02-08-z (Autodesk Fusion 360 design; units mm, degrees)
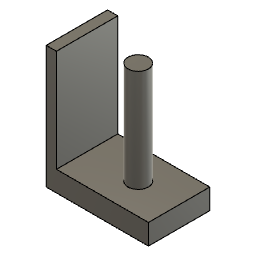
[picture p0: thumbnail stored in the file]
sketch "スケッチ1" plane through (0, 0, 0) normal (0, 1, 0) x axis (1, 0, 0)
  line L1 (50, 15) -> (0, 15)
  line L2 (50, -15) -> (50, 15)
  line L3 (0, -15) -> (50, -15)
  line L4 (0, 15) -> (0, -15)
  point P1 (0, 0)
  point P2 (0, 15)
  point P3 (50, 15)
  point P5 (0, -15)
  horizontal L1
  vertical L2
  horizontal L3
  vertical L4
  midpoint P1 L4
  dimension "d7" distance P2 P3 = 50
  dimension "d8" distance P2 P5 = 30
extrude "押し出し1" new body sketch "スケッチ1" along normal blind 10
sketch "スケッチ3" plane through (0, 10, 0) normal (0, 1, 0) x axis (-1, 0, 0)
  line L1 (-50, 15) -> (0, 15)
  line L2 (-50, -15) -> (-50, 15)
  line L3 (0, -15) -> (-50, -15)
  line L4 (0, 15) -> (0, -15)
  line L5 (-5, -15) -> (0, -15)
  line L6 (-5, 15) -> (-5, -15)
  line L7 (0, 15) -> (-5, 15)
  line L8 (0, -15) -> (0, 15)
  point P6 (0, -15)
  point P7 (-5, -15)
  horizontal L5
  vertical L6
  horizontal L7
  vertical L8
  collinear L3 L5
  collinear L4 L8
  collinear L1 L7
  dimension "d11" distance P6 P7 = 5
extrude "押し出し3" add sketch "スケッチ3" profile of L1 L3 L4 L5 L6 L7 L8 along normal blind 50
sketch "スケッチ2" plane through (0, 10, 0) normal (0, 1, 0) x axis (-1, 0, 0)
  line L1 (-50, 15) -> (-5, 15)
  line L2 (-50, -15) -> (-50, 15)
  line L3 (-5, -15) -> (-50, -15)
  line L4 (-5, 15) -> (-5, -15)
  circle C1 centre (-30, 0) radius 5
  point P1 (0, 0)
  point P6 (-30, 0)
  horizontal P1 P6
  dimension "d9" diameter C1 = 10
extrude "押し出し2" add sketch "スケッチ2" profile of C1 to an object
